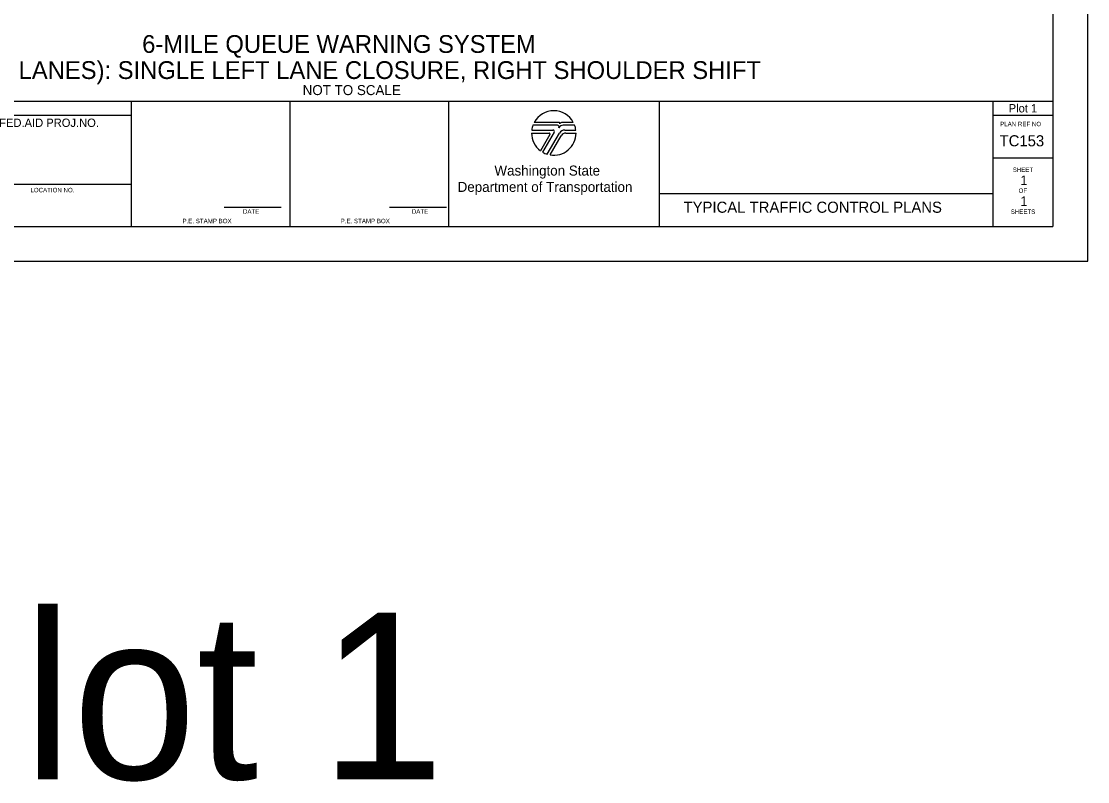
# Model space of a CAD drawing. Extents: x 99999.1 to 100035.7, y 99995 to 100010.7.
# Drawn here: x 100006.46 to 100016.06, y 99995.01 to 100001.84 of the extents above; entities that cross this region are included whole.
import ezdxf

# ---------------------------------------------------------------- set-up
doc = ezdxf.new("R2010")
doc.units = 0
for name, color, linetype in [('SH_DE_DetailHeading1Text', 7, 'Continuous'), ('SH_DE_DetailHeading3Text', 7, 'Continuous'), ('SH_GI_PlotLimits', 7, 'Continuous'), ('SH_GI_SheetBorder', 7, 'Continuous'), ('SH_GI_SheetLocationText', 7, 'Continuous'), ('SH_GI_SheetTextInCells', 7, 'Continuous'), ('SH_GI_TitleBlockText', 7, 'Continuous'), ('SH_GI_WSDOTLogo', 7, 'Continuous')]:
    doc.layers.add(name, color=color, linetype=linetype)

msp = doc.modelspace()

# ---------------------------------------------------------------- linework, layer by layer
at = {"layer": 'SH_GI_PlotLimits'}
msp.add_lwpolyline([(99999.0625, 99999.6875), (100016.0625, 99999.6875), (100016.0625, 100010.6875), (99999.0625, 100010.6875)], close=True, dxfattribs=at)
at = {"layer": 'SH_GI_SheetBorder'}
for p, q in [((100015.75, 100010.375), (100015.75, 100000)), ((100000, 100001.1259), (100015.75, 100001.1259)), ((100007.4566, 100000), (100007.4566, 100001.1259)), ((100008.8828, 100000), (100008.8828, 100001.1259)), ((100010.3089, 100001.1259), (100010.3089, 100000)), ((100012.2055, 100001.1259), (100012.2055, 100000)), ((100015.2079, 100001.1259), (100015.2079, 100000)), ((100000, 100001.0008), (100007.4566, 100001.0008)), ((100015.2079, 100001.0008), (100015.75, 100001.0008)), ((100015.2079, 100000.6176), (100015.75, 100000.6176)), ((100007.4566, 100000.3753), (100005.4466, 100000.3753)), ((100012.2055, 100000.2955), (100015.2079, 100000.2955)), ((100008.2903, 100000.1733), (100008.802, 100000.1733)), ((100009.7797, 100000.1733), (100010.2914, 100000.1733)), ((100000, 100000), (100015.75, 100000))]:
    msp.add_line(p, q, dxfattribs=at)
at = {"layer": 'SH_GI_WSDOTLogo'}
for p, q in [((100011.059, 100000.8661), (100011.2496, 100000.8661)), ((100011.2894, 100000.9094), (100011.0697, 100000.9094)), ((100011.303, 100000.9354), (100011.0815, 100000.9354)), ((100011.433, 100000.9354), (100011.3351, 100000.9354)), ((100011.343, 100000.9094), (100011.3429, 100000.9094)), ((100011.4448, 100000.9094), (100011.343, 100000.9094)), ((100011.3558, 100000.8661), (100011.4555, 100000.8661)), ((100011.0572, 100000.84), (100011.2148, 100000.84)), ((100011.222, 100000.8277), (100011.1364, 100000.6807)), ((100011.261, 100000.8464), (100011.1567, 100000.6672)), ((100011.1989, 100000.6487), (100011.3089, 100000.839)), ((100011.2244, 100000.6428), (100011.3242, 100000.8156)), ((100011.3655, 100000.8394), (100011.4572, 100000.8394))]:
    msp.add_line(p, q, dxfattribs=at)
for centre, radius, start, end in [((100011.2572, 100000.84), 0.2, 28.47865, 151.53204), ((100011.2572, 100000.84), 0.2, 159.69598, 172.50569), ((100011.2497, 100000.853), 0.0131, 329.76834, 90), ((100011.2894, 100000.8946), 0.0148, 327.8418, 89.99855), ((100011.3429, 100000.861), 0.0484, 89.99529, 147.82376), ((100011.303, 100000.9263), 0.00903, 329.87418, 90.00328), ((100011.3558, 100000.8119), 0.0542, 90, 149.99738), ((100011.3352, 100000.9066), 0.0287, 90.00721, 148.16763), ((100011.2572, 100000.84), 0.2, 7.49431, 20.29406), ((100011.2572, 100000.84), 0.2, 179.99864, 232.84327), ((100011.2149, 100000.8318), 0.0082, 329.74356, 90), ((100011.2572, 100000.84), 0.2, 260.54554, 359.80857), ((100011.3654, 100000.7918), 0.0476, 90, 150.05432), ((100011.2572, 100000.84), 0.2, 239.79292, 253.0448)]:
    msp.add_arc(centre, radius, start, end, dxfattribs=at)

# ---------------------------------------------------------------- texts
at = {"layer": 'SH_DE_DetailHeading1Text'}
for s, p in [('6-MILE QUEUE WARNING SYSTEM', (100007.5522, 100001.5606)), ('FREEWAY (2 LANES): SINGLE LEFT LANE CLOSURE, RIGHT SHOULDER SHIFT', (100005.073, 100001.3259))]:
    msp.add_text(s, height=0.16, rotation=360, dxfattribs=at).set_placement(p)
at = {"layer": 'SH_DE_DetailHeading3Text'}
msp.add_text('NOT TO SCALE', height=0.09, dxfattribs=at).set_placement((100008.9969, 100001.1809))
at = {"layer": 'SH_GI_SheetBorder'}
msp.add_text('PLAN REF NO', height=0.040032, dxfattribs=at).set_placement((100015.2747, 100000.9008))
at = {"layer": 'SH_GI_SheetLocationText'}
for height, p in [(0.075, (100015.3518, 100001.025)), (1.5, (100005.1422, 99995.0267))]:
    msp.add_text('Plot 1', height=height, dxfattribs=at).set_placement(p)
at = {"layer": 'SH_GI_SheetTextInCells'}
for s, height, p in [('FED.AID PROJ.NO.', 0.07506, (100006.2652, 100000.8945)), ('Washington State', 0.090072, (100010.7229, 100000.4571)), ('SHEET', 0.04003, (100015.3877, 100000.4896)), ('Department of Transportation', 0.090072, (100010.3916, 100000.3101)), ('LOCATION NO.', 0.040032, (100006.5465, 100000.3067)), ('OF', 0.04003, (100015.4406, 100000.3008)), ('DATE', 0.04003, (100008.4597, 100000.1141)), ('DATE', 0.04003, (100009.9794, 100000.1141)), ('SHEETS', 0.04003, (100015.3698, 100000.112)), ('P.E. STAMP BOX', 0.040032, (100007.915, 100000.0286)), ('P.E. STAMP BOX', 0.040032, (100009.339, 100000.0286))]:
    msp.add_text(s, height=height, dxfattribs=at).set_placement(p)
at = {"layer": 'SH_GI_TitleBlockText'}
for s, height, p in [('TC153', 0.1, (100015.2697, 100000.72)), ('1', 0.085, (100015.4566, 100000.3723)), ('TYPICAL TRAFFIC CONTROL PLANS', 0.1, (100012.4251, 100000.1224)), ('1', 0.085, (100015.4566, 100000.1843))]:
    msp.add_text(s, height=height, dxfattribs=at).set_placement(p)

doc.saveas('drawing.dxf')
